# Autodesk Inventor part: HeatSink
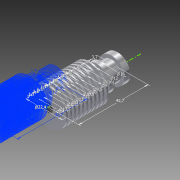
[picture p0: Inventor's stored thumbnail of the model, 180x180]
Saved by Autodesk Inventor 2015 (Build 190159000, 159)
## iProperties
Created: 2015-02
Part Number: HeatSink
Material: Типовые
Document SubType Name: Modeling
Designer: Parabolik
Density: 1 g/cm^3
Appearance: По умолчанию
Author: Parabolik
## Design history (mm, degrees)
sketch "Эскиз1"
  geometry: L1 (-6, 39)-(-6, 33); L2 (-8, 33)-(-8, 30); L3 (-4.5, 30)-(-4.5, 28.5); L4 (-4.75, 25)-(-4.75, 23.5); L5 (-5, 22.5)-(-5, 21); L6 (-4.5, 27.5)-(-4.5, 26); L7 (-8, 39)-(-6, 39); L8 (-8, 42.7)-(-8, 39); L9 (0, 42.7)-(-8, 42.7); L10 (-11.2, 23.5)-(-11.2, 22.5); L11 (-11.2, 21)-(-11.2, 20); L12 (-8, 28.5)-(-8, 27.5); L13 (-11.2, 20)-(-5.25, 20); L14 (-5, 21)-(-11.2, 21); L15 (-11.2, 22.5)-(-5, 22.5); L16 (-4.75, 23.5)-(-11.2, 23.5); L17 (-11.2, 25)-(-4.75, 25); L18 (-8, 27.5)-(-4.5, 27.5); L19 (-4.5, 28.5)-(-8, 28.5); L20 (-8, 30)-(-4.5, 30); L21 (-4.5, 26)-(-11.2, 26); L22 (-11.2, 26)-(-11.2, 25); L23 (-5.5, 17.5)-(-5.5, 16); L24 (-5.25, 20)-(-5.25, 18.5); L25 (-6, 33)-(-8, 33); L26 (-5.25, 18.5)-(-11.2, 18.5); L27 (-11.2, 18.5)-(-11.2, 17.5); L28 (-11.2, 17.5)-(-5.5, 17.5); L29 (-11.2, 16)-(-11.2, 15); L30 (-11.2, 15)-(-5.75, 15); L31 (-5.75, 13.5)-(-11.2, 13.5); L32 (-5.75, 15)-(-5.75, 13.5); L33 (-5.5, 16)-(-11.2, 16); L34 (-11.2, 8.5)-(-11.2, 7.5); L35 (-6.5, 6)-(-11.2, 6); L36 (-11.2, 6)-(-11.2, 5); L37 (-11.2, 5)-(-6.75, 5); L38 (-6.75, 5)-(-6.75, 3.5); L39 (-6.75, 3.5)-(-11.2, 3.5); L40 (-11.2, 2.5)-(-7, 2.5); L41 (-11.2, 3.5)-(-11.2, 2.5); L42 (-11.2, 0)-(0, 0); L43 (-7, 2.5)-(-7, 1); L44 (-11.2, 1)-(-11.2, 0); L45 (-7, 1)-(-11.2, 1); L46 (-11.2, 13.5)-(-11.2, 12.5); L47 (-11.2, 11)-(-11.2, 10); L48 (-11.2, 10)-(-6.25, 10); L49 (-6.25, 10)-(-6.25, 8.5); L50 (-6.25, 8.5)-(-11.2, 8.5); L51 (-11.2, 11)-(-6, 11); L52 (0, 57)-(0, -13); L53 (-11.2, 12.5)-(-6, 12.5); L54 (-6, 12.5)-(-6, 11); L55 (-11.2, 7.5)-(-6.5, 7.5); L56 (-6.5, 7.5)-(-6.5, 6); L57 (0, 42.7)-(0, 0)
  constraints: 115 end point, 27 point on line, 2 horizontal, 2 perpendicular, 1 collinear, 1 vertical
  dimensions: "d13" = 1.5 distance between parallel lines of L33 L28; "d14" = 1.5 distance between parallel lines of L26 L13; "d15" = 1.5 distance between parallel lines of L14 L15; "d16" = 1.5 distance between parallel lines of L16 L17; "d17" = 1.5 distance between parallel lines of L21 L18; "d18" = 1.5 distance between parallel lines of L19 L20; "d19" = 3.7 distance between parallel lines of L7 L9; "d20" = 6 distance between parallel lines of L25 L7; "d21" = 3 distance between parallel lines of L20 L25; "d32" = 16 diameter of L8 L52; "d33" = 12 diameter of L1 L52; "d34" = 1 distance between parallel lines of L18 L19; "d35" = 1 distance between parallel lines of L17 L21; "d36" = 1 distance between parallel lines of L15 L16; "d37" = 1 distance between parallel lines of L13 L14; "d38" = 1 distance between parallel lines of L28 L26; "d39" = 1 distance between parallel lines of L30 L33; "d40" = 1.5 distance between parallel lines of L31 L30; "d43" = 1 distance between parallel lines of L48 L51; "d44" = 1.5 distance between parallel lines of L50 L48; "d47" = 1 distance between parallel lines of L37 L35; "d48" = 1.5 distance between parallel lines of L39 L37; "d49" = 1 distance between parallel lines of L40 L39; "d50" = 1.5 distance between parallel lines of L45 L40; "d51" = 1 distance between parallel lines of L42 L45; "d52" = 22.4 diameter of L44 L52; "d53" = 16 diameter of L2 L52 (derived); "d54" = 9 diameter of L3 L52; "d55" = 9.5 diameter of L4 L52; "d56" = 10 diameter of L5 L52; "d57" = 10.5 diameter of L24 L52; "d58" = 11 diameter of L23 L52; "d61" = 12.5 diameter of L49 L52; "d63" = 13.5 diameter of L38 L52; "d64" = 14 diameter of L43 L52; "d66" = 11.5 diameter of L32 L52; "d67" = 1 distance between parallel lines of L31 L53; "d68" = 12 diameter of L54 L52 (derived); "d69" = 13 diameter of L56 L52; "d70" = 1.5 distance between parallel lines of L35 L55; "d71" = 1.5 distance between parallel lines of L51 L53; "d99" = 42.7 distance between parallel lines of L9 L42
revolve "Вращение1" stored, may be unused: angle "d30" = 90 deg
sketch "Эскиз2"
  geometry: 3 further points
  constraints: 1 coincident
hole "Отверстие1" sketch "Эскиз2" diameter "d78" = 4; stored, may be unused: countersink angle "d82" = 90 deg, drill point angle "d84" = 0 deg; dims "d79" = 6, "d80" = 4, "d81" = 2, "d83" = 8
hole "Отверстие3" sketch "Эскиз2" diameter "d92" = 5.917; stored, may be unused: countersink angle "d96" = 90 deg, drill point angle "d98" = 118 deg; dims "d93" = 14, "d94" = 4.4, "d95" = 2, "d97" = 16
sketch "Эскиз3"
  geometry: 2 further points
  constraints: 1 coincident
hole "Отверстие4" sketch "Эскиз3" at (0, 0) diameter "d100" = 8; stored, may be unused: countersink angle "d104" = 90 deg, drill point angle "d106" = 118 deg; dims "d101" = 6, "d102" = 4, "d103" = 2, "d105" = 8
node "Твердое тело1"
